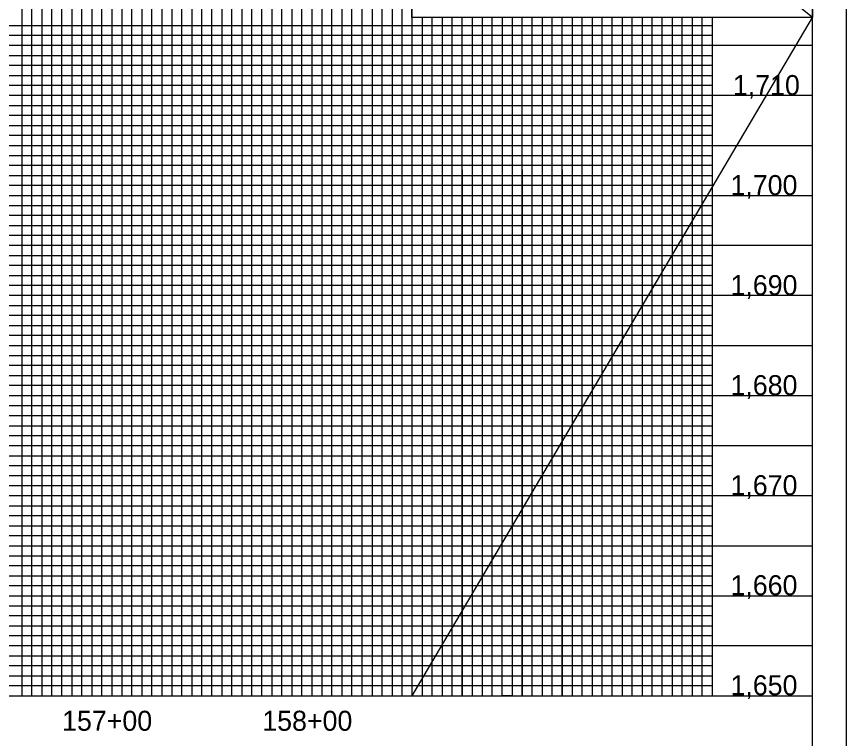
# Model space of a CAD drawing. Extents: x 505602 to 507286, y 483109 to 484209.
# Drawn here: x 506871.5 to 507286.1, y 483662.4 to 484023.2 of the extents above; entities that cross this region are included whole.
import ezdxf

# ---------------------------------------------------------------- set-up
doc = ezdxf.new("R2010")
doc.units = 0
for name, color, linetype in [('Exist Vertical Profile Vertical Axis Label', 7, 'Continuous'), ('Scratch_Level_4', 7, 'Continuous'), ('Sheet Layout Profile Border Port 1', 7, 'Continuous'), ('Sheet Plot Border Outside CELL', 7, 'Continuous'), ('Sheet Profile CELL', 7, 'Continuous'), ('Sheet Profile Grid Major CELL', 7, 'Continuous'), ('Sheet Profile Grid Middle CELL', 7, 'Continuous'), ('Sheet Profile Grid Minor CELL', 7, 'Continuous'), ('Sheet Sticker Exception Certification CELL', 7, 'Continuous')]:
    doc.layers.add(name, color=color, linetype=linetype)

msp = doc.modelspace()

# ---------------------------------------------------------------- linework, layer by layer
at = {"layer": 'Scratch_Level_4'}
msp.add_lwpolyline([(507269.08, 483683.71), (507269.07, 484022.66), (507069.03, 484022.66), (507069.03, 484142), (507016.54, 484142), (507016.54, 484183.71), (505818.69, 484183.71), (505818.69, 483683.71)], close=True, dxfattribs=at)
at = {"layer": 'Sheet Layout Profile Border Port 1'}
msp.add_lwpolyline([(505819.08, 484183.71), (505819.08, 483683.71), (507069.08, 483683.71), (507269.07, 484022.66), (507269.07, 484022.66), (507069.08, 484183.71)], close=True, dxfattribs=at)
at = {"layer": 'Sheet Plot Border Outside CELL'}
msp.add_lwpolyline([(505602.08, 483108.71), (507286.08, 483108.71), (507286.08, 484208.71), (505602.08, 484208.71)], close=True, dxfattribs=at)
at = {"layer": 'Sheet Profile CELL'}
msp.add_line((505769.08, 483683.71), (507269.08, 483683.71), dxfattribs=at)
msp.add_lwpolyline([(507269.08, 484183.71), (505769.08, 484183.71), (505769.08, 483133.71), (507269.08, 483133.71)], close=True, dxfattribs=at)
at = {"layer": 'Sheet Profile Grid Major CELL'}
for points in [[(506869.08, 484183.71), (506919.08, 484183.71), (506919.08, 483683.71), (506969.08, 483683.71), (506969.08, 484183.71), (507019.08, 484183.71), (507019.08, 483683.71), (507069.08, 483683.71), (507069.08, 484183.71), (507095.38, 484183.71)], [(507219.08, 484022.66), (507219.08, 483683.71), (507269.08, 483683.71), (507269.08, 484033.71)], [(507119.08, 484022.66), (507119.08, 483683.71), (507169.08, 483683.71), (507169.08, 483683.71), (507169.08, 484022.66)], [(507269.08, 483983.71), (505769.08, 483983.71), (505769.08, 483933.71), (507269.08, 483933.71)], [(507269.08, 483883.71), (505769.08, 483883.71), (505769.08, 483833.71), (507269.08, 483833.71)], [(507269.08, 483783.71), (505769.08, 483783.71), (505769.08, 483783.71), (505769.08, 483733.71), (507269.08, 483733.71)]]:
    msp.add_lwpolyline(points, dxfattribs=at)
at = {"layer": 'Sheet Profile Grid Middle CELL'}
for points in [[(506844.08, 483683.71), (506894.08, 483683.71), (506894.08, 484183.71), (506944.08, 484183.71), (506944.08, 483683.71), (506994.08, 483683.71), (506994.08, 484183.71), (507044.08, 484183.71), (507044.08, 483683.71), (507094.08, 483683.71), (507094.08, 484022.66)], [(507094.08, 483946.51), (507094.08, 483683.71), (507144.08, 483683.71), (507144.08, 484022.66)], [(507144.08, 483946.51), (507144.08, 483683.71), (507194.08, 483683.71), (507194.08, 484022.66)], [(507269.08, 484008.71), (505769.08, 484008.71), (505769.08, 483958.71), (507094.08, 483958.71)], [(507094.08, 483958.71), (507269.08, 483958.71)], [(507269.08, 483908.71), (505769.08, 483908.71), (505769.08, 483858.71), (507269.08, 483858.71)], [(507269.08, 483808.71), (505769.08, 483808.71), (505769.08, 483758.71), (507269.08, 483758.71)], [(507269.08, 483708.71), (505769.08, 483708.71)]]:
    msp.add_lwpolyline(points, dxfattribs=at)
at = {"layer": 'Sheet Profile Grid Minor CELL'}
for p, q in [((505819.08, 484018.71), (507219.08, 484018.71)), ((507219.08, 483998.71), (505819.08, 483998.71)), ((505819.08, 483993.71), (507219.08, 483993.71)), ((507219.08, 483973.71), (505819.08, 483973.71)), ((505819.08, 483968.71), (507219.08, 483968.71)), ((507219.08, 483948.71), (505819.08, 483948.71)), ((505819.08, 483943.71), (507219.08, 483943.71)), ((507219.08, 483938.71), (505819.08, 483938.71)), ((505819.08, 483928.71), (507219.08, 483928.71)), ((507219.08, 483923.71), (505819.08, 483923.71)), ((505819.08, 483918.71), (507219.08, 483918.71)), ((507219.08, 483913.71), (505819.08, 483913.71)), ((505819.08, 483903.71), (507219.08, 483903.71)), ((507219.08, 483898.71), (505819.08, 483898.71)), ((505819.08, 483893.71), (507219.08, 483893.71)), ((507219.08, 483888.71), (505819.08, 483888.71)), ((505819.08, 483878.71), (507219.08, 483878.71)), ((507219.08, 483873.71), (505819.08, 483873.71)), ((505819.08, 483868.71), (507219.08, 483868.71)), ((507219.08, 483863.71), (505819.08, 483863.71)), ((505819.08, 483853.71), (507219.08, 483853.71)), ((507219.08, 483848.71), (505819.08, 483848.71)), ((505819.08, 483843.71), (507219.08, 483843.71)), ((507219.08, 483838.71), (505819.08, 483838.71)), ((505819.08, 483828.71), (507219.08, 483828.71)), ((507219.08, 483823.71), (505819.08, 483823.71)), ((505819.08, 483818.71), (507219.08, 483818.71)), ((507219.08, 483813.71), (505819.08, 483813.71)), ((505819.08, 483803.71), (507219.08, 483803.71)), ((507219.08, 483798.71), (505819.08, 483798.71)), ((507219.08, 483793.71), (505819.08, 483793.71)), ((507219.08, 483788.71), (505819.08, 483788.71)), ((505819.08, 483778.71), (507219.08, 483778.71)), ((507219.08, 483773.71), (505819.08, 483773.71)), ((505819.08, 483768.71), (507219.08, 483768.71)), ((507219.08, 483763.71), (505819.08, 483763.71)), ((505819.08, 483753.71), (507219.08, 483753.71)), ((507219.08, 483748.71), (505819.08, 483748.71)), ((505819.08, 483743.71), (507219.08, 483743.71)), ((507219.08, 483738.71), (505819.08, 483738.71)), ((505819.08, 483728.71), (507219.08, 483728.71)), ((507219.08, 483723.71), (505819.08, 483723.71)), ((505819.08, 483718.71), (507219.08, 483718.71)), ((507219.08, 483713.71), (505819.08, 483713.71)), ((505819.08, 483703.71), (507219.08, 483703.71)), ((507219.08, 483698.71), (505819.08, 483698.71)), ((505819.08, 483693.71), (507219.08, 483693.71))]:
    msp.add_line(p, q, dxfattribs=at)
for points in [[(506874.08, 484183.71), (506874.08, 483683.71), (506879.08, 483683.71), (506879.08, 484183.71)], [(506884.08, 484183.71), (506884.08, 483683.71), (506889.08, 483683.71), (506889.08, 484183.71)], [(506899.08, 484183.71), (506899.08, 483683.71), (506904.08, 483683.71), (506904.08, 484183.71)], [(506909.08, 484183.71), (506909.08, 483683.71), (506914.08, 483683.71), (506914.08, 484183.71)], [(506924.08, 484183.71), (506924.08, 483683.71), (506929.08, 483683.71), (506929.08, 484183.71)], [(506934.08, 484183.71), (506934.08, 483683.71), (506939.08, 483683.71), (506939.08, 484183.71)], [(506949.08, 484183.71), (506949.08, 483683.71), (506954.08, 483683.71), (506954.08, 484183.71)], [(506959.08, 484183.71), (506959.08, 483683.71)], [(506959.08, 483683.71), (506964.08, 483683.71), (506964.08, 484183.71)], [(506974.08, 484183.71), (506974.08, 483683.71), (506979.08, 483683.71), (506979.08, 484183.71)], [(506984.08, 484183.71), (506984.08, 483683.71), (506989.08, 483683.71), (506989.08, 484183.71)], [(506999.08, 484183.71), (506999.08, 483683.71), (507004.08, 483683.71), (507004.08, 484183.71)], [(507009.08, 484183.71), (507009.08, 483683.71), (507014.08, 483683.71), (507014.08, 484183.71)], [(507024.08, 484183.71), (507024.08, 483683.71), (507029.08, 483683.71), (507029.08, 484183.71)], [(507034.08, 484183.71), (507034.08, 483683.71), (507039.08, 483683.71), (507039.08, 484183.71)], [(507049.08, 484183.71), (507049.08, 483683.71), (507054.08, 483683.71), (507054.08, 484183.71)], [(507059.08, 484183.71), (507059.08, 483683.71), (507064.08, 483683.71), (507064.08, 484183.71)], [(507074.08, 484022.66), (507074.08, 483683.71), (507079.08, 483683.71), (507079.08, 484022.66)], [(507084.08, 484022.66), (507084.08, 483683.71), (507089.08, 483683.71), (507089.08, 484022.66)], [(507099.08, 484022.66), (507099.08, 483683.71), (507099.08, 483683.71), (507104.08, 483683.71), (507109.08, 483683.71), (507109.08, 484022.66)], [(507104.08, 484022.66), (507104.08, 483683.71)], [(507114.07, 484022.66), (507113.98, 483683.76), (507118.98, 483683.76), (507124.08, 483683.71), (507124.08, 484022.66)], [(507124.08, 483946.51), (507124.08, 483683.71), (507129.08, 483683.71), (507129.08, 484022.66)], [(507134.08, 484022.66), (507134.08, 483683.71), (507139.08, 483683.71), (507139.08, 484022.66)], [(507149.08, 484022.66), (507149.08, 483683.71), (507154.08, 483683.71), (507154.08, 484022.66)], [(507159.08, 484022.66), (507159.08, 483683.71), (507164.08, 483683.71), (507164.08, 484022.66)], [(507174.08, 484022.66), (507174.08, 483683.71), (507179.08, 483683.71), (507179.08, 484022.66)], [(507184.08, 484022.66), (507184.08, 483683.71), (507189.08, 483683.71), (507189.08, 484022.66)], [(507199.08, 484022.66), (507199.08, 483683.71), (507204.08, 483683.71), (507204.08, 484022.66)], [(507209.08, 484022.66), (507209.08, 483683.71), (507214.08, 483683.71), (507214.08, 484022.66)], [(507219.08, 484013.71), (505819.08, 484013.71), (505819.08, 484003.71), (507219.08, 484003.71)], [(507219.08, 483988.71), (505819.08, 483988.71), (505819.08, 483978.71), (507219.08, 483978.71)], [(507219.08, 483963.71), (505819.08, 483963.71), (505819.08, 483953.71), (507219.08, 483953.71)], [(507219.08, 483688.71), (505819.08, 483688.71)]]:
    msp.add_lwpolyline(points, dxfattribs=at)
at = {"layer": 'Sheet Sticker Exception Certification CELL'}
for p, q in [((507069.03, 484022.66), (507069.03, 484046.16)), ((507069.03, 484022.66), (507069.03, 484046.16)), ((507269.07, 484046.15), (507269.07, 484022.65)), ((507269.07, 484046.15), (507269.07, 484022.65)), ((507269.07, 484022.66), (507069.03, 484022.66)), ((507269.07, 484022.66), (507069.03, 484022.66))]:
    msp.add_line(p, q, dxfattribs=at)

# ---------------------------------------------------------------- texts
at = {"layer": 'Exist Vertical Profile Vertical Axis Label'}
for s, p in [('1,710', (507229.36, 483983.96)), ('1,700', (507228.17, 483933.96)), ('1,690', (507228.17, 483883.96)), ('1,680', (507228.17, 483833.96)), ('1,670', (507228.17, 483783.96)), ('1,660', (507228.17, 483733.96)), ('1,650', (507228.17, 483683.96)), ('157+00', (506894.26, 483666.21)), ('158+00', (506994.26, 483666.21))]:
    msp.add_text(s, height=10, dxfattribs=at).set_placement(p)

doc.saveas('drawing.dxf')
